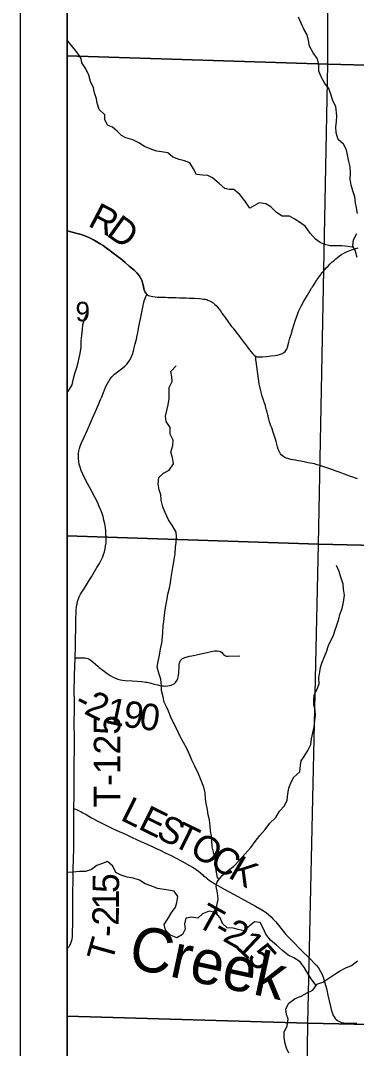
# Model space of a CAD drawing. Extents: x 0 to 34, y 0 to 22.
# Drawn here: x 23.417 to 24.137, y 17.712 to 19.917 of the extents above; entities that cross this region are included whole.
import ezdxf

# ---------------------------------------------------------------- set-up
doc = ezdxf.new("R2010")
doc.units = 0
for name, color, linetype in [('GM_X_Corporation', 7, 'Continuous'), ('GM_X_County_Road', 7, 'Continuous'), ('GM_X_County_Road_Text', 7, 'Continuous'), ('GM_X_Minor_River', 7, 'Continuous'), ('GM_X_Minor_River_Text', 7, 'Continuous'), ('GM_X_Section_Text', 7, 'Continuous'), ('GM_X_Township_Road', 7, 'Continuous'), ('GM_X_Township_Road_Text', 7, 'Continuous'), ('SH_Data', 7, 'Continuous')]:
    doc.layers.add(name, color=color, linetype=linetype)

msp = doc.modelspace()

# ---------------------------------------------------------------- linework, layer by layer
at = {"layer": 'GM_X_Corporation'}
for points in [[(30.3167, 20.9), (23.5167, 20.9), (23.5167, 14.7114), (24.6586, 14.6808), (24.6805, 14.6799), (26.0522, 14.6391), (26.4447, 14.6283), (26.4468, 14.6272), (26.4498, 14.6263), (26.4544, 14.6257), (26.5226, 14.6248), (26.5325, 14.6248), (26.5616, 14.6241), (26.5684, 14.624), (26.5727, 14.624), (26.5813, 14.6239), (26.5991, 14.6234), (26.6128, 14.6229), (26.6208, 14.6225), (26.6337, 14.622), (26.643, 14.6216), (26.6535, 14.621), (27.01, 14.6164)], [(26.0759, 17.6934), (26.0747, 17.7146), (25.4012, 17.7333), (25.0619, 17.7438), (25.0668, 18.5474), (25.0701, 18.7696), (25.0847, 19.8351), (25.0988, 20.7425), (24.9808, 20.7443), (24.1323, 20.7702), (24.1208, 20.7707), (23.5167, 20.7862), (23.5167, 14.7114)]]:
    msp.add_lwpolyline(points, dxfattribs=at)
for points in [[(23.5167, 20.7848), (23.5167, 19.8409), (24.0758, 19.8228), (24.0752, 20.7675)], [(24.0752, 20.7675), (24.1192, 20.7694), (25.0966, 20.7402), (25.0844, 19.7972), (24.0758, 19.8228)], [(23.5167, 19.8409), (23.5167, 18.8111), (24.0555, 18.7938), (24.0758, 19.8228)], [(25.0844, 19.7972), (25.0685, 18.7697), (24.0555, 18.7938), (24.0758, 19.8228)], [(23.5167, 18.8111), (23.5167, 17.7813), (24.0329, 17.7663), (24.0555, 18.7938)], [(25.0685, 18.7697), (25.0591, 17.7438), (24.0329, 17.7663), (24.0555, 18.7938)], [(23.5167, 17.7813), (23.5167, 16.7576), (24.0196, 16.7435), (24.0329, 17.7663)], [(24.0329, 17.7663), (25.0591, 17.7438), (25.0442, 16.7237), (24.0196, 16.7435)]]:
    msp.add_lwpolyline(points, close=True, dxfattribs=at)
at = {"layer": 'GM_X_County_Road'}
for points in [[(23.5167, 19.4656), (23.5242, 19.4637), (23.538, 19.4601), (23.5468, 19.4574), (23.5567, 19.4539), (23.5647, 19.4506), (23.573, 19.4465), (23.5806, 19.4423), (23.5874, 19.438), (23.5935, 19.4338), (23.6012, 19.4286), (23.6062, 19.425), (23.61, 19.4219), (23.6119, 19.4204), (23.6181, 19.4158), (23.6201, 19.4143), (23.6225, 19.4125), (23.6269, 19.4091), (23.6307, 19.4059), (23.6408, 19.3977), (23.6499, 19.3901), (23.6601, 19.3811), (23.6658, 19.3755), (23.6711, 19.3695), (23.6742, 19.3644), (23.6765, 19.3594), (23.6782, 19.3542), (23.6801, 19.3463), (23.6813, 19.3414), (23.6827, 19.3372), (23.6842, 19.3342), (23.6855, 19.3321), (23.687, 19.3301), (23.6878, 19.3294)], [(23.9214, 19.1964), (23.9221, 19.196), (23.9241, 19.1955), (23.9267, 19.1953), (23.9348, 19.1955), (23.9442, 19.1961), (23.9534, 19.1973), (23.9626, 19.1982), (23.9669, 19.1988), (23.9718, 19.2), (23.976, 19.2014), (23.9789, 19.2028), (23.9816, 19.2046), (23.9839, 19.2067), (23.986, 19.2092), (23.9875, 19.2114), (23.9883, 19.2131), (23.9891, 19.2159), (23.9921, 19.2266), (23.9945, 19.2356), (23.9957, 19.2391), (23.996, 19.2397), (23.9964, 19.2415), (23.9975, 19.2444), (23.9979, 19.2462), (24.0003, 19.2539), (24.0031, 19.2634), (24.0064, 19.2747), (24.0096, 19.2839), (24.0128, 19.2925), (24.0148, 19.2969), (24.0182, 19.304), (24.024, 19.3148), (24.0318, 19.3279), (24.0409, 19.3424), (24.0419, 19.3439), (24.0429, 19.3454), (24.0448, 19.3485), (24.0468, 19.3516), (24.0503, 19.3571), (24.0522, 19.3601), (24.0531, 19.3615), (24.0543, 19.3632), (24.0549, 19.364), (24.059, 19.3697), (24.0597, 19.3706), (24.061, 19.3724), (24.0624, 19.3742), (24.0638, 19.3761), (24.0664, 19.3793), (24.0691, 19.3825), (24.0724, 19.3861), (24.0763, 19.39), (24.0805, 19.3945), (24.0852, 19.3988), (24.089, 19.4022), (24.093, 19.4057), (24.0962, 19.4084), (24.101, 19.4119), (24.1052, 19.4146), (24.1101, 19.4176), (24.1141, 19.4197), (24.1195, 19.422), (24.1264, 19.4245), (24.1406, 19.4291)], [(23.6878, 19.3294), (23.6891, 19.3284), (23.691, 19.3271), (23.6937, 19.3261), (23.6967, 19.3251), (23.7005, 19.3244), (23.7055, 19.3238), (23.7099, 19.3235), (23.7143, 19.3233), (23.7211, 19.3232), (23.7273, 19.323), (23.7323, 19.3229), (23.7366, 19.3227), (23.7441, 19.3225), (23.7503, 19.3223), (23.7577, 19.3221), (23.7652, 19.3217), (23.772, 19.3216), (23.7782, 19.3214), (23.79, 19.321), (23.7999, 19.3204), (23.8054, 19.3199), (23.8094, 19.3193), (23.8133, 19.3187), (23.8159, 19.318), (23.8185, 19.317), (23.8219, 19.3157), (23.8257, 19.3138), (23.8298, 19.3111), (23.8334, 19.3079), (23.836, 19.3053), (23.8393, 19.3016), (23.8452, 19.2937), (23.8485, 19.2892), (23.851, 19.2857), (23.8553, 19.2796), (23.862, 19.2706), (23.8694, 19.2606), (23.8724, 19.2567), (23.8747, 19.2538), (23.8808, 19.2459), (23.8842, 19.2415), (23.8898, 19.2341), (23.8961, 19.2256), (23.8999, 19.2207), (23.9052, 19.2138), (23.9106, 19.2069), (23.915, 19.2016), (23.9177, 19.1989), (23.9203, 19.197), (23.9214, 19.1964)]]:
    msp.add_lwpolyline(points, dxfattribs=at)
at = {"layer": 'GM_X_Minor_River'}
for points in [[(24.1397, 19.5028), (24.137, 19.5149), (24.1354, 19.5248), (24.1334, 19.5388), (24.1296, 19.5517), (24.1261, 19.5638), (24.1237, 19.5767), (24.1244, 19.5896), (24.1239, 19.6025), (24.1208, 19.6146), (24.1177, 19.6283), (24.1157, 19.6393), (24.1095, 19.6514), (24.0977, 19.6612), (24.0934, 19.6759), (24.093, 19.6888), (24.0944, 19.6995), (24.0947, 19.7124), (24.0931, 19.7321), (24.0862, 19.7446), (24.0827, 19.7567), (24.078, 19.7707), (24.0696, 19.7817), (24.0619, 19.7945), (24.0561, 19.8082), (24.0564, 19.8218), (24.0537, 19.8343), (24.0445, 19.8472), (24.0361, 19.8616), (24.0345, 19.8741), (24.0314, 19.8858), (24.0241, 19.8983), (24.0183, 19.9112), (24.0129, 19.9237)], [(24.1301, 19.4315), (24.1281, 19.4306), (24.1186, 19.4317), (24.1061, 19.4335), (24.0807, 19.4333), (24.0685, 19.4359), (24.059, 19.4404), (24.0491, 19.4475), (24.0381, 19.4603), (24.0277, 19.4751), (24.0174, 19.483), (24.0037, 19.4912), (23.9938, 19.4969), (23.9779, 19.4971), (23.9653, 19.5046), (23.9535, 19.5171), (23.9428, 19.5235), (23.9288, 19.5253), (23.9182, 19.5199), (23.9084, 19.5145), (23.8977, 19.53), (23.887, 19.5432), (23.8744, 19.5545), (23.8649, 19.5544), (23.855, 19.5567), (23.8425, 19.5672), (23.828, 19.5789), (23.8181, 19.5841), (23.8075, 19.5852), (23.7942, 19.5866), (23.7873, 19.5987), (23.7796, 19.6112), (23.7682, 19.6157), (23.7568, 19.6186), (23.7431, 19.6235), (23.7324, 19.6325), (23.7188, 19.6347), (23.7089, 19.6361), (23.6979, 19.6399), (23.6823, 19.6466), (23.6701, 19.6545), (23.6572, 19.6605), (23.6427, 19.6649), (23.6332, 19.6702), (23.6237, 19.6792), (23.6138, 19.6879), (23.6031, 19.6924), (23.5977, 19.7045), (23.5973, 19.714), (23.5851, 19.726), (23.5812, 19.7393), (23.5796, 19.7488), (23.5754, 19.7617), (23.573, 19.7726), (23.5665, 19.7855), (23.563, 19.7995), (23.5564, 19.8132), (23.548, 19.8256), (23.5464, 19.8351), (23.5384, 19.8483), (23.5261, 19.8627), (23.5167, 19.8746)], [(24.1385, 19.4083), (24.135, 19.4211), (24.1292, 19.4332), (24.131, 19.4465), (24.1378, 19.4595)], [(23.5167, 19.1181), (23.5183, 19.1205), (23.5277, 19.1354), (23.5303, 19.1491), (23.5328, 19.1593), (23.5373, 19.1727), (23.5399, 19.1829), (23.5421, 19.1932), (23.5443, 19.2027), (23.5469, 19.216), (23.5468, 19.2297), (23.5478, 19.2414), (23.5493, 19.254), (23.5503, 19.2638), (23.554, 19.2764), (23.5585, 19.2886)], [(23.8423, 18.0744), (23.8389, 18.0789), (23.837, 18.0891), (23.8358, 18.099), (23.8349, 18.1119), (23.8333, 18.1217), (23.8279, 18.1445), (23.8266, 18.1581), (23.8262, 18.1676), (23.8242, 18.1786), (23.8234, 18.1881), (23.8218, 18.2021), (23.8194, 18.2127), (23.8175, 18.2237), (23.8151, 18.2374), (23.8135, 18.2476), (23.8123, 18.2601), (23.8096, 18.2726), (23.8042, 18.287), (23.798, 18.3006), (23.7907, 18.3177), (23.7841, 18.3305), (23.7795, 18.3407), (23.7738, 18.354), (23.7665, 18.368), (23.7584, 18.3824), (23.7519, 18.3967), (23.7442, 18.4119), (23.7392, 18.4228), (23.7342, 18.435), (23.7295, 18.4448), (23.7249, 18.455), (23.7226, 18.4664), (23.7191, 18.4796), (23.719, 18.4895), (23.7174, 18.5039), (23.7131, 18.5172), (23.71, 18.5297), (23.7118, 18.5422), (23.7144, 18.5555), (23.7166, 18.5692), (23.7195, 18.5814), (23.7213, 18.5947), (23.7216, 18.6042), (23.7227, 18.6182), (23.7241, 18.6277), (23.7252, 18.6414), (23.7266, 18.6524), (23.7292, 18.6649), (23.731, 18.6763), (23.7324, 18.6866), (23.7358, 18.6995), (23.738, 18.7109), (23.7394, 18.7219), (23.742, 18.7352), (23.7442, 18.7478), (23.7463, 18.76), (23.7485, 18.7736), (23.7492, 18.7869), (23.7503, 18.7968), (23.7509, 18.8097), (23.7501, 18.8196), (23.7424, 18.8328), (23.734, 18.8457), (23.7271, 18.8615), (23.7221, 18.8737), (23.7182, 18.8877), (23.7173, 18.8994), (23.7142, 18.91), (23.7119, 18.9229), (23.7129, 18.9362), (23.7231, 18.9458), (23.7352, 18.9523), (23.7446, 18.9657), (23.7426, 18.9793), (23.7391, 18.9911), (23.7435, 19.0048), (23.7438, 19.0165), (23.7373, 19.0298), (23.7372, 19.0438), (23.7288, 19.0563), (23.7272, 19.0684), (23.7305, 19.0802), (23.7331, 19.0927), (23.7353, 19.106), (23.7351, 19.1292), (23.7415, 19.1421), (23.741, 19.1524), (23.739, 19.1641), (23.7507, 19.176)], [(23.8384, 17.9992), (23.8379, 18.0071), (23.8378, 18.0189), (23.8404, 18.0314), (23.8392, 18.0458), (23.8364, 18.0595), (23.8382, 18.0694), (23.8484, 18.082), (23.8601, 18.0923), (23.874, 18.1026), (23.8865, 18.1156), (23.8977, 18.1286), (23.9105, 18.1431), (23.9199, 18.1557), (23.9301, 18.1687), (23.9414, 18.1817), (23.9515, 18.195), (23.9639, 18.2076), (23.9718, 18.2206), (23.9831, 18.232), (23.9883, 18.2446), (23.9901, 18.2579), (23.9923, 18.2704), (23.996, 18.2803), (24.0028, 18.2937), (24.016, 18.3055), (24.0174, 18.3192), (24.0185, 18.3287), (24.0252, 18.3382), (24.0331, 18.3508), (24.0391, 18.3641), (24.0405, 18.3763), (24.0438, 18.3888), (24.0464, 18.4021), (24.0478, 18.4147), (24.0493, 18.4257), (24.0484, 18.4378), (24.0457, 18.4496), (24.0456, 18.4621), (24.0474, 18.4716), (24.0523, 18.4811), (24.0568, 18.4941), (24.0567, 18.5066), (24.0585, 18.5195), (24.0599, 18.529), (24.0629, 18.5385), (24.067, 18.5488), (24.0726, 18.5629), (24.0774, 18.5762), (24.0823, 18.5869), (24.0879, 18.5979), (24.0909, 18.6078), (24.0942, 18.6177), (24.099, 18.6325), (24.1012, 18.6424), (24.1065, 18.6557), (24.1094, 18.6694), (24.1116, 18.6838), (24.1096, 18.6967), (24.1084, 18.7077), (24.1034, 18.7229), (24.1002, 18.7346), (24.0945, 18.7475)], [(23.7967, 17.9917), (23.783, 17.9935), (23.7709, 17.9915), (23.7683, 17.9789), (23.7699, 17.9676), (23.7643, 17.9565), (23.7515, 17.9492), (23.7386, 17.9548), (23.7279, 17.9654), (23.7244, 17.9779), (23.7326, 17.9901), (23.7394, 18.0023), (23.7488, 18.0152), (23.7521, 18.0248), (23.7543, 18.0377), (23.7462, 18.0494), (23.7337, 18.0516), (23.7106, 18.0552), (23.698, 18.0601), (23.684, 18.0653), (23.6718, 18.0732), (23.6585, 18.0773), (23.6452, 18.0795), (23.6327, 18.0835), (23.6212, 18.0895), (23.6147, 18.1028), (23.6033, 18.1126), (23.5904, 18.1079), (23.5806, 18.1041), (23.5689, 18.096), (23.556, 18.0918), (23.5428, 18.0917), (23.5295, 18.0897), (23.5167, 18.0896)], [(23.992, 17.7018), (23.9874, 17.7128), (23.9843, 17.7227), (23.9819, 17.7344), (23.9818, 17.7466), (23.9882, 17.7607), (23.9908, 17.7747), (23.9873, 17.7846), (23.9853, 17.7967), (23.9924, 17.8089), (24.0056, 17.8192), (24.0185, 17.8239), (24.0317, 17.8312), (24.0434, 17.8369), (24.0505, 17.8469), (24.0417, 17.8593), (24.0337, 17.8714), (24.026, 17.8847), (24.0165, 17.8979), (24.0031, 17.9061), (23.991, 17.9121), (23.9788, 17.9219), (23.9654, 17.9332), (23.9524, 17.9445), (23.9425, 17.9573), (23.9371, 17.9702), (23.9306, 17.9819), (23.9184, 17.9838), (23.9067, 17.9742), (23.8966, 17.9639), (23.8833, 17.9672), (23.873, 17.9702), (23.8598, 17.9708), (23.8498, 17.9799), (23.8448, 17.9924), (23.8345, 18.0033), (23.8209, 18.0066), (23.8072, 18.0005), (23.7967, 17.9917)], [(24.0505, 17.8469), (24.0524, 17.8495), (24.0649, 17.8538), (24.0909, 17.8714), (24.1008, 17.8776), (24.1144, 17.8849), (24.1265, 17.8899), (24.1397, 17.8998)]]:
    msp.add_lwpolyline(points, dxfattribs=at)
at = {"layer": 'GM_X_Township_Road'}
for points in [[(23.6878, 19.3294), (23.687, 19.3301), (23.6855, 19.3321), (23.6842, 19.3342), (23.6827, 19.3372), (23.6813, 19.3414), (23.6801, 19.3463), (23.6782, 19.3542), (23.6765, 19.3594), (23.6742, 19.3644), (23.6711, 19.3695), (23.6658, 19.3755), (23.6601, 19.3811), (23.6499, 19.3901), (23.6408, 19.3977), (23.6307, 19.4059), (23.6269, 19.4091), (23.6225, 19.4125), (23.6201, 19.4143), (23.6181, 19.4158), (23.6119, 19.4204), (23.61, 19.4219), (23.6062, 19.425), (23.6012, 19.4286), (23.5935, 19.4338), (23.5874, 19.438), (23.5806, 19.4423), (23.573, 19.4465), (23.5647, 19.4506), (23.5567, 19.4539), (23.5468, 19.4574), (23.538, 19.4601), (23.5242, 19.4637), (23.5167, 19.4656)], [(23.5341, 18.5494), (23.5344, 18.5743), (23.5345, 18.5812), (23.5347, 18.5961), (23.535, 18.6054), (23.5352, 18.6203), (23.5355, 18.6345), (23.5358, 18.645), (23.5361, 18.6517), (23.5368, 18.6591), (23.5379, 18.6659), (23.539, 18.6707), (23.5407, 18.676), (23.5426, 18.6806), (23.5454, 18.6861), (23.5535, 18.6994), (23.5643, 18.7168), (23.5685, 18.7237), (23.5805, 18.7433), (23.5859, 18.7524), (23.5897, 18.7595), (23.5928, 18.7663), (23.5949, 18.7715), (23.5965, 18.7768), (23.5981, 18.7835), (23.5992, 18.7896), (23.6, 18.7964), (23.6003, 18.8019), (23.6003, 18.8075), (23.5999, 18.8155), (23.5993, 18.8223), (23.5985, 18.8284), (23.5972, 18.837), (23.5956, 18.845), (23.5935, 18.8527), (23.5915, 18.8593), (23.5889, 18.8663), (23.5856, 18.8743), (23.5814, 18.8833), (23.5758, 18.8944), (23.5689, 18.9076), (23.5603, 18.9234), (23.554, 18.9355), (23.55, 18.9439), (23.5469, 18.9514), (23.5443, 18.959), (23.5427, 18.965), (23.5415, 18.9711), (23.5408, 18.9773), (23.5407, 18.9829), (23.5411, 18.9884), (23.5418, 18.9927), (23.5432, 18.9988), (23.5447, 19.0035), (23.5475, 19.0111), (23.5521, 19.0219), (23.5599, 19.0389), (23.5687, 19.0587), (23.5709, 19.0638), (23.5772, 19.078), (23.5839, 19.0933), (23.5883, 19.1035), (23.5909, 19.1098), (23.5945, 19.119), (23.599, 19.1299), (23.603, 19.1383), (23.6057, 19.1432), (23.6087, 19.1479), (23.6126, 19.1527), (23.6179, 19.1579), (23.6237, 19.1626), (23.6357, 19.1715), (23.6405, 19.1754), (23.6445, 19.1794), (23.6477, 19.1831), (23.6506, 19.1872), (23.6533, 19.1921), (23.6554, 19.1972), (23.6572, 19.2025), (23.6597, 19.2115), (23.6626, 19.223), (23.665, 19.2332), (23.6668, 19.241), (23.6682, 19.2477), (23.6707, 19.2598), (23.6721, 19.2665), (23.6748, 19.2805), (23.6782, 19.2982), (23.6819, 19.3155), (23.6831, 19.3193), (23.6844, 19.3225), (23.6852, 19.3246), (23.686, 19.326), (23.6873, 19.3285), (23.6878, 19.3294)], [(24.1391, 18.9338), (24.1274, 18.9379), (24.1245, 18.9389), (24.1175, 18.9415), (24.1093, 18.9444), (24.1023, 18.947), (24.0936, 18.9502), (24.0843, 18.9537), (24.0691, 18.959), (24.0585, 18.9624), (24.0531, 18.964), (24.0472, 18.9656), (24.0339, 18.9683), (24.0253, 18.97), (24.0205, 18.9709), (24.018, 18.9713), (24.0125, 18.9724), (24.0058, 18.9734), (24.0016, 18.9742), (24.0004, 18.9745), (23.9961, 18.9753), (23.9919, 18.9764), (23.9901, 18.977), (23.9866, 18.9781), (23.9832, 18.9797), (23.9811, 18.981), (23.9785, 18.9828), (23.9759, 18.9853), (23.974, 18.9874), (23.9725, 18.9898), (23.9715, 18.9919), (23.971, 18.993), (23.9705, 18.9941), (23.9691, 18.9975), (23.9677, 19.0023), (23.9648, 19.0137), (23.9637, 19.0185), (23.9586, 19.0338), (23.9553, 19.0432), (23.9538, 19.0472), (23.9509, 19.0561), (23.9495, 19.0615), (23.9488, 19.0638), (23.9475, 19.0686), (23.9468, 19.071), (23.9454, 19.0764), (23.9443, 19.0806), (23.9434, 19.0841), (23.9431, 19.0853), (23.9417, 19.0906), (23.9407, 19.0942), (23.9394, 19.0983), (23.9386, 19.1006), (23.9381, 19.1023), (23.9366, 19.1064), (23.9349, 19.1111), (23.9332, 19.1164), (23.9319, 19.1222), (23.9304, 19.1287), (23.9288, 19.1375), (23.9217, 19.1853), (23.9212, 19.1891), (23.921, 19.192), (23.9211, 19.1938), (23.9213, 19.1954), (23.9214, 19.1964)], [(23.5341, 18.5494), (23.5414, 18.5495), (23.5432, 18.5495), (23.5457, 18.5495), (23.55, 18.5495), (23.5543, 18.5494), (23.558, 18.5491), (23.5612, 18.5484), (23.564, 18.5469), (23.5677, 18.5446), (23.5718, 18.5413), (23.5831, 18.531), (23.5856, 18.5291), (23.5929, 18.5234), (23.6015, 18.5172), (23.6092, 18.512), (23.6151, 18.5086), (23.6201, 18.5061), (23.6253, 18.5041), (23.6307, 18.5025), (23.6356, 18.5015), (23.6411, 18.5009), (23.6559, 18.5002), (23.6671, 18.4998), (23.677, 18.4989), (23.6844, 18.4978), (23.688, 18.4972), (23.6941, 18.4959), (23.7031, 18.4935), (23.711, 18.4915), (23.7152, 18.4906), (23.7193, 18.49), (23.7207, 18.4899), (23.723, 18.4897), (23.728, 18.4893), (23.7324, 18.4896), (23.7361, 18.4901), (23.7397, 18.491), (23.7414, 18.4917), (23.7447, 18.4932), (23.7462, 18.4943), (23.7489, 18.4968), (23.7505, 18.4987), (23.7525, 18.5018), (23.754, 18.5052), (23.7549, 18.5081), (23.7557, 18.5124), (23.7562, 18.5179), (23.7567, 18.5303), (23.7572, 18.5352), (23.7579, 18.5388), (23.7589, 18.5417), (23.76, 18.5439), (23.7619, 18.5463), (23.7642, 18.5482), (23.7658, 18.5492), (23.7692, 18.5505), (23.7769, 18.5525), (23.7792, 18.5531), (23.784, 18.5543), (23.8131, 18.5607), (23.8252, 18.5632), (23.8326, 18.5645), (23.8363, 18.5649), (23.8394, 18.5648), (23.8424, 18.5642), (23.8453, 18.563), (23.8483, 18.5609), (23.8522, 18.557), (23.8542, 18.5555), (23.8564, 18.5542), (23.8581, 18.5536), (23.86, 18.5532), (23.8618, 18.5532), (23.8869, 18.5543)], [(23.5311, 18.2266), (23.5312, 18.2354), (23.5314, 18.2466), (23.5316, 18.262), (23.5317, 18.2817), (23.5317, 18.2953), (23.5315, 18.3077), (23.5322, 18.3693), (23.532, 18.4176), (23.5321, 18.4313), (23.5322, 18.448), (23.5322, 18.4567), (23.5321, 18.4617), (23.5318, 18.4741), (23.5324, 18.5126), (23.5341, 18.5494)], [(23.5167, 17.927), (23.5185, 17.9285), (23.5207, 17.9308), (23.5225, 17.9333), (23.524, 17.9356), (23.5247, 17.9377), (23.526, 17.9419), (23.5271, 17.9467), (23.5279, 17.9523), (23.5284, 17.9604), (23.5286, 17.9796), (23.5288, 17.9989), (23.5291, 18.0418), (23.5296, 18.0778), (23.5296, 18.0902), (23.5297, 18.0996), (23.53, 18.1157), (23.5306, 18.1437), (23.5308, 18.1654), (23.5308, 18.1859), (23.5308, 18.1996), (23.5309, 18.2113), (23.5311, 18.2266)], [(23.5311, 18.2266), (23.538, 18.2237), (23.5425, 18.2216), (23.5458, 18.2199), (23.549, 18.2181), (23.5571, 18.2134), (23.5691, 18.2069), (23.5839, 18.199), (23.5983, 18.1917), (23.6111, 18.1854), (23.6235, 18.1797), (23.6416, 18.1714), (23.65, 18.1675), (23.6562, 18.1647), (23.6749, 18.1561), (23.6884, 18.15), (23.7002, 18.1444), (23.7058, 18.1417), (23.7159, 18.1369), (23.7266, 18.1318), (23.7394, 18.1255), (23.7488, 18.1207), (23.7624, 18.1133), (23.7788, 18.1045), (23.7869, 18.0998), (23.7931, 18.0958), (23.7981, 18.0921), (23.8074, 18.084), (23.8094, 18.0825), (23.8127, 18.0797), (23.8137, 18.079), (23.8166, 18.0766), (23.822, 18.0725), (23.8291, 18.0676), (23.8334, 18.0649), (23.8398, 18.0612), (23.8551, 18.0529), (23.8736, 18.0428), (23.8987, 18.0291), (23.9205, 18.017), (23.9339, 18.0092), (23.9433, 18.0032), (23.9491, 17.9985), (23.9542, 17.9939), (23.9581, 17.99), (23.9639, 17.9835), (23.9808, 17.9628), (23.986, 17.9567), (23.9906, 17.9516), (24.0025, 17.9389), (24.0164, 17.9247), (24.0391, 17.9025), (24.0457, 17.8959), (24.0507, 17.8905), (24.0555, 17.8847), (24.0596, 17.8785), (24.0629, 17.8719), (24.0656, 17.8649), (24.0694, 17.8524), (24.0727, 17.8404), (24.076, 17.8265), (24.0811, 17.8022), (24.0836, 17.7926), (24.0855, 17.7867), (24.0873, 17.7827), (24.0891, 17.7795), (24.0913, 17.7765), (24.0939, 17.7739), (24.0963, 17.7719), (24.099, 17.7703), (24.1024, 17.7688), (24.1053, 17.7679), (24.1102, 17.767), (24.1151, 17.7665), (24.1214, 17.7664), (24.1381, 17.7665)]]:
    msp.add_lwpolyline(points, dxfattribs=at)
at = {"layer": 'SH_Data'}
for points in [[(23.4167, 21), (30.4167, 21), (30.4167, 14), (23.4167, 14)], [(23.5167, 20.9), (30.3167, 20.9), (30.3167, 14.1), (23.5167, 14.1)]]:
    msp.add_lwpolyline(points, close=True, dxfattribs=at)

# ---------------------------------------------------------------- texts
at = {"layer": 'GM_X_County_Road_Text'}
for s, rotation, p in [('R', 332.4208, (23.5589, 19.4774)), ('D', 324.2616, (23.5984, 19.4569))]:
    msp.add_text(s, height=0.0568, rotation=rotation, dxfattribs=at).set_placement(p)
at = {"layer": 'GM_X_Minor_River_Text'}
msp.add_text('Creek', height=0.09469, rotation=347.8692, dxfattribs=at).set_placement((23.6443, 17.8862))
at = {"layer": 'GM_X_Section_Text'}
msp.add_text('9', height=0.0419, rotation=0, dxfattribs=at).set_placement((23.5345, 19.2715))
at = {"layer": 'GM_X_Township_Road_Text'}
for s, height, rotation, p in [('2', 0.0568, 333.7365, (23.5504, 18.4312)), ('-', 0.0568, 332.9481, (23.5289, 18.4422)), ('1', 0.0568, 347.7297, (23.596, 18.4107)), ('9', 0.0568, 351.9242, (23.6347, 18.4025)), ('0', 0.0568, 352.0809, (23.6695, 18.3976)), ('T-125', 0.05682, 90, (23.6306, 18.2285)), ('L', 0.0568, 333.7435, (23.6287, 18.203)), ('E', 0.0568, 333.7438, (23.6668, 18.1842)), ('S', 0.0568, 333.7453, (23.7049, 18.1654)), ('T', 0.0568, 333.6937, (23.7393, 18.1485)), ('O', 0.0568, 328.7657, (23.7763, 18.1303)), ('C', 0.0568, 328.9025, (23.8192, 18.1043)), ('K', 0.0568, 329.5954, (23.8598, 18.0798)), ('5', 0.0568, 89.568, (23.6278, 18.0452)), ('1', 0.0568, 89.6364, (23.6275, 18.0102)), ('2', 0.0568, 89.3949, (23.6272, 17.975)), ('T', 0.0568, 330.7027, (23.7907, 17.9765)), ('-', 0.0568, 88.9454, (23.6267, 17.9511)), ('-', 0.0568, 330.669, (23.8277, 17.9557)), ('2', 0.0568, 330.5269, (23.848, 17.9443)), ('T', 0.0568, 74.2188, (23.6128, 17.8945)), ('1', 0.0568, 316.7629, (23.8756, 17.9292)), ('5', 0.0568, 311.2662, (23.9001, 17.9063))]:
    msp.add_text(s, height=height, rotation=rotation, dxfattribs=at).set_placement(p)

doc.saveas('drawing.dxf')
